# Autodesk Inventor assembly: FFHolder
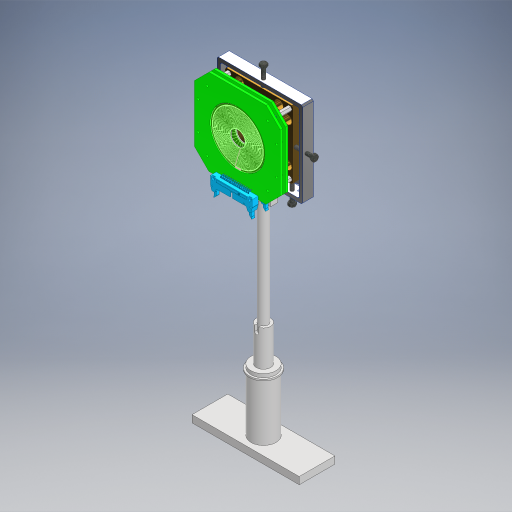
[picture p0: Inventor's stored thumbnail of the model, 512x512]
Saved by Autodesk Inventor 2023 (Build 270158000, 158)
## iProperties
Created: 2024-01
Part Number: FFHolder
Document SubType Name: Assembly
Designer: tornqvih
Author: tornqvih
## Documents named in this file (12)
- \\Mac\Home\Documents\chalmers\Inventor2023\FFHolder\FFHolder.iam
- \\Mac\Home\Documents\chalmers\Inventor2023\TargetHolder\StandFoot.ipt
- \\Mac\Home\Documents\chalmers\Inventor2023\FFHolder\Shim.ipt
- \\Mac\Home\Documents\chalmers\Inventor2023\FFHolder\S3Mount.ipt
- \\Mac\Home\Documents\chalmers\Inventor2023\FFHolder\S3Adjuster.ipt
- \\Mac\Home\Documents\Inventor\Content Center Files\R2023\en-US\ISO 4016\ISO 4016 - M5 x 25.ipt
- \\Mac\Home\Documents\chalmers\Inventor2023\FFHolder\Standoff.ipt
- \\Mac\Home\Documents\Inventor\Content Center Files\R2023\en-US\ISO 4762(2)\ISO 4762 - M5 x 20ISO.ipt
- \\Mac\Home\Documents\Inventor\Content Center Files\R2023\en-US\ISO 7093 A\ISO 7093 A - ST 6 - 140 HV .ipt
- \\Mac\Home\Documents\chalmers\Inventor2023\FFHolder\Leg.ipt
- \\Mac\Home\Documents\chalmers\Inventor2023\A-3330.iam
- \\Mac\Home\Documents\chalmers\Inventor2023\FFHolder\Fork.ipt
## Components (25 placed, 12 different names)
1. StandFoot:1 — Mate:35, Mate:36
2. Shim:1 — Mate:37, Insert:20, Angle:4, Mate:38, Insert:25
3. S3Mount:1
4. S3Adjuster:1
5. ISO 4016 M5 x 25:1 — Mate:5, Mate:10
6. ISO 4016 M5 x 25:2 — Mate:6, Mate:11
7. ISO 4016 M5 x 25:3 — Mate:7, Mate:12
8. ISO 4016 M5 x 25:4 — Mate:8, Mate:13
9. ISO 4016 M5 x 25:5 — Mate:9, Mate:14
10. Standoff:1 — Insert:1, Insert:19
11. Standoff:2 — Insert:2
12. Standoff:3 — Insert:18
13. Standoff:4 — Insert:23
14. ISO 7093 A ST 6 - 140 HV - A:1 — Mate:28, Mate:31
15. ISO 7093 A ST 6 - 140 HV - A:2 — Mate:30, Mate:33
16. ISO 7093 A ST 6 - 140 HV - A:3 — Mate:27, Mate:32
17. ISO 7093 A ST 6 - 140 HV - A:4 — Mate:29, Mate:34
18. ISO 4762 M5 x 20:1 — Mate:19, Mate:31
19. ISO 4762 M5 x 20:2 — Mate:20, Mate:33
20. ISO 4762 M5 x 20:3 — Mate:21, Mate:32
21. ISO 4762 M5 x 20:4 — Mate:22, Mate:34
22. Leg:1 — Mate:35, Mate:36, Angle:2, Insert:24
23. A-3330_1000 [sub-assembly] — Mate:37, Insert:19, Insert:20, Angle:3
24. A-3330_65 [sub-assembly] — Mate:38, Insert:25, Angle:5
25. Fork:1 — Insert:21, Insert:22, Insert:24
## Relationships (40: Mate 26, Insert 10, Angle 4)
- Mate:5: ISO 4016 M5 x 25:1
- Mate:6: ISO 4016 M5 x 25:2
- Mate:7: ISO 4016 M5 x 25:3
- Mate:8: ISO 4016 M5 x 25:4
- Mate:9: ISO 4016 M5 x 25:5
- Mate:10: ISO 4016 M5 x 25:1
- Mate:11: ISO 4016 M5 x 25:2
- Mate:12: ISO 4016 M5 x 25:3
- Mate:13: ISO 4016 M5 x 25:4
- Mate:14: ISO 4016 M5 x 25:5
- Insert:1: Standoff:1
- Insert:2: Standoff:2
- Insert:18: Standoff:3
- Insert:23: Standoff:4
- Mate:19: ISO 4762 M5 x 20:1
- Mate:20: ISO 4762 M5 x 20:2
- Mate:21: ISO 4762 M5 x 20:3
- Mate:22: ISO 4762 M5 x 20:4
- Mate:27: ISO 7093 A ST 6 - 140 HV - A:3
- Mate:28: ISO 7093 A ST 6 - 140 HV - A:1
- Mate:29: ISO 7093 A ST 6 - 140 HV - A:4
- Mate:30: ISO 7093 A ST 6 - 140 HV - A:2
- Mate:31: ISO 7093 A ST 6 - 140 HV - A:1 ↔ ISO 4762 M5 x 20:1
- Mate:32: ISO 7093 A ST 6 - 140 HV - A:3 ↔ ISO 4762 M5 x 20:3
- Mate:33: ISO 7093 A ST 6 - 140 HV - A:2 ↔ ISO 4762 M5 x 20:2
- Mate:34: ISO 7093 A ST 6 - 140 HV - A:4 ↔ ISO 4762 M5 x 20:4
- Mate:35: StandFoot:1 ↔ Leg:1
- Mate:36: StandFoot:1 ↔ Leg:1
- Mate:37: Shim:1 ↔ A-3330_1000
- Insert:19: Standoff:1 ↔ A-3330_1000
- Insert:20: Shim:1 ↔ A-3330_1000
- Insert:21: Fork:1
- Insert:22: Fork:1
- Angle:2: Leg:1
- Insert:24: Leg:1 ↔ Fork:1
- Angle:3: A-3330_1000
- Angle:4: Shim:1
- Mate:38: Shim:1 ↔ A-3330_65
- Insert:25: Shim:1 ↔ A-3330_65
- Angle:5: A-3330_65
